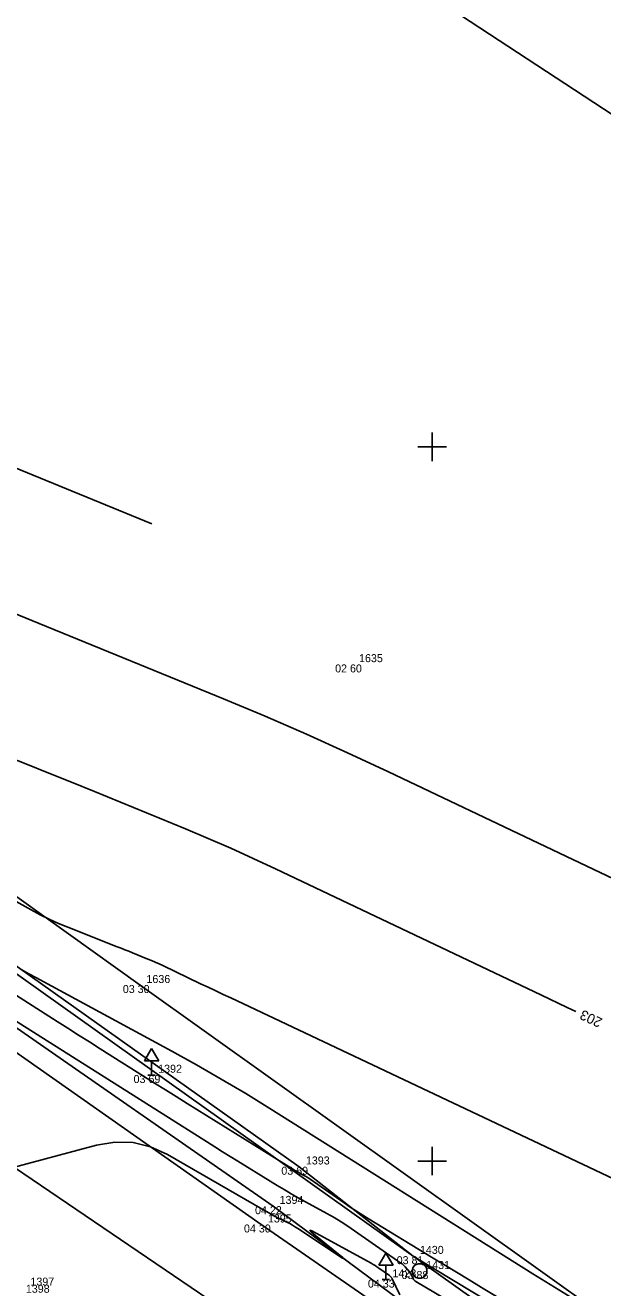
# Model space of a CAD drawing. Extents: x -711234 to -710007, y -1026313 to -1025448.
# Drawn here: x -710514.24 to -710494.03, y -1025579.43 to -1025535.25 of the extents above; entities that cross this region are included whole.
import ezdxf

# ---------------------------------------------------------------- set-up
doc = ezdxf.new("R2010")
doc.units = 0
for name, color, linetype in [('Ex_Contour Labels', 7, 'Continuous'), ('Ex_Major Contours', 7, 'Continuous'), ('Ex_Minor Contours', 7, 'Continuous'), ('Z_body', 7, 'Continuous'), ('Z_body_cisla', 7, 'Continuous'), ('Z_body_vysky_redukovane', 7, 'Continuous'), ('Z_dopravni_znacky', 7, 'Continuous'), ('Z_hektometricka_sit', 7, 'Continuous'), ('Z_hrany_paty', 7, 'Continuous'), ('Z_katastr_hranice', 7, 'Continuous'), ('Z_komunikace', 7, 'Continuous'), ('Z_komunikace_osa', 7, 'Continuous'), ('Z_pole_rozhranni', 7, 'Continuous'), ('Z_site_kanalizace_znaky', 7, 'Continuous')]:
    doc.layers.add(name, color=color, linetype=linetype)

# ---------------------------------------------------------------- blocks, each defined once
blk = doc.blocks.new('POINT_DISPLAY')
blk.add_line((0, 0), (0, 0))
blk = doc.blocks.new('Z620')
for p, q in [((-0.25, 0.05), (-0.23, 0.13)), ((-0.25, -0.05), (-0.25, 0.05)), ((-0.23, 0.13), (-0.17, 0.2)), ((-0.17, 0.2), (-0.05, 0.25)), ((-0.05, 0.25), (0.05, 0.25)), ((0.05, 0.25), (0.17, 0.2)), ((0.17, 0.2), (0.23, 0.13)), ((0.23, 0.13), (0.25, 0.05)), ((0.25, 0.05), (0.25, -0.05)), ((-0.2, -0.17), (-0.25, -0.05)), ((-0.13, -0.23), (-0.2, -0.17)), ((-0.05, -0.25), (-0.13, -0.23)), ((0.05, -0.25), (-0.05, -0.25)), ((0.13, -0.23), (0.05, -0.25)), ((0.2, -0.17), (0.13, -0.23)), ((0.25, -0.05), (0.2, -0.17))]:
    blk.add_line(p, q)
blk = doc.blocks.new('Z527')
for p, q in [((0, 0.93), (-0.25, 0.5)), ((0.25, 0.5), (0, 0.93)), ((-0.25, 0.5), (0.25, 0.5)), ((0, 0), (0, 0.5)), ((-0.13, 0), (0.13, 0))]:
    blk.add_line(p, q)

msp = doc.modelspace()

# ---------------------------------------------------------------- linework, layer by layer
at = {"layer": 'Ex_Major Contours'}
for points in [[(-710515.021, -1025560.786), (-710514.219, -1025561.103), (-710513.418, -1025561.422), (-710512.619, -1025561.744), (-710511.821, -1025562.07), (-710508.631, -1025563.378), (-710507.836, -1025563.71), (-710507.045, -1025564.053), (-710506.26, -1025564.407), (-710505.479, -1025564.772), (-710496.199, -1025569.186), (-710495.275, -1025569.625), (-710494.974, -1025569.768)], [(-710517.324, -1025568.366), (-710507.868, -1025574.338), (-710507.601, -1025574.506), (-710507.334, -1025574.674), (-710507.066, -1025574.841), (-710506.798, -1025575.008), (-710505.675, -1025575.705), (-710505.43, -1025575.855), (-710505.184, -1025576.001), (-710504.936, -1025576.144), (-710504.687, -1025576.284), (-710503.684, -1025576.837), (-710503.435, -1025576.978), (-710503.19, -1025577.126), (-710502.95, -1025577.28), (-710502.713, -1025577.441), (-710501.092, -1025578.573), (-710501.052, -1025578.603), (-710501.015, -1025578.634), (-710500.98, -1025578.668), (-710500.947, -1025578.705), (-710500.799, -1025578.878), (-710500.778, -1025578.905), (-710500.758, -1025578.932), (-710500.741, -1025578.961), (-710500.725, -1025578.992), (-710500.666, -1025579.115), (-710500.65, -1025579.144), (-710500.63, -1025579.169), (-710500.606, -1025579.192), (-710500.578, -1025579.211), (-710495.929, -1025581.975)]]:
    msp.add_lwpolyline(points, dxfattribs=at)
at = {"layer": 'Ex_Minor Contours'}
for points in [[(-710543.059, -1025536.078), (-710542.36, -1025536.464), (-710541.661, -1025536.849), (-710540.962, -1025537.234), (-710540.263, -1025537.62), (-710537.467, -1025539.162), (-710536.768, -1025539.548), (-710536.07, -1025539.935), (-710535.372, -1025540.323), (-710534.675, -1025540.712), (-710523.071, -1025547.206), (-710522.657, -1025547.429), (-710522.235, -1025547.637), (-710521.807, -1025547.831), (-710521.372, -1025548.01), (-710519.619, -1025548.698), (-710519.181, -1025548.871), (-710518.743, -1025549.045), (-710518.307, -1025549.222), (-710517.871, -1025549.399), (-710509.81, -1025552.704)], [(-710490.545, -1025566.606), (-710501.528, -1025561.382), (-710502.96, -1025560.713), (-710504.4, -1025560.064), (-710505.849, -1025559.435), (-710507.306, -1025558.825), (-710513.755, -1025556.182), (-710514.918, -1025555.708), (-710516.083, -1025555.238), (-710517.249, -1025554.773), (-710518.417, -1025554.312), (-710523.552, -1025552.297), (-710524.484, -1025551.913), (-710525.402, -1025551.498), (-710526.304, -1025551.052), (-710527.192, -1025550.575), (-710530.715, -1025548.603), (-710531.596, -1025548.111), (-710532.478, -1025547.62), (-710533.36, -1025547.131), (-710534.244, -1025546.643), (-710543.487, -1025541.545)], [(-710521.316, -1025562.171), (-710514.038, -1025566.212), (-710513.723, -1025566.38), (-710513.403, -1025566.537), (-710513.078, -1025566.684), (-710512.748, -1025566.82), (-710511.02, -1025567.498), (-710510.886, -1025567.55), (-710510.753, -1025567.604), (-710510.62, -1025567.657), (-710510.487, -1025567.712), (-710509.955, -1025567.93), (-710509.823, -1025567.985), (-710509.691, -1025568.042), (-710509.56, -1025568.101), (-710509.43, -1025568.162), (-710508.104, -1025568.793), (-710507.839, -1025568.918), (-710507.575, -1025569.044), (-710507.311, -1025569.169), (-710507.046, -1025569.294), (-710492.348, -1025576.24)], [(-710488.428, -1025585.358), (-710498.27, -1025579.421), (-710498.709, -1025579.156), (-710499.148, -1025578.891), (-710499.587, -1025578.625), (-710500.025, -1025578.36), (-710502.209, -1025577.035), (-710502.431, -1025576.898), (-710502.65, -1025576.758), (-710502.868, -1025576.614), (-710503.083, -1025576.466), (-710504.275, -1025575.634), (-710504.321, -1025575.603), (-710504.367, -1025575.573), (-710504.415, -1025575.544), (-710504.463, -1025575.517), (-710504.657, -1025575.41), (-710504.705, -1025575.383), (-710504.753, -1025575.355), (-710504.801, -1025575.327), (-710504.848, -1025575.298), (-710508.577, -1025572.983), (-710508.958, -1025572.746), (-710509.338, -1025572.508), (-710509.718, -1025572.27), (-710510.097, -1025572.031), (-710511.614, -1025571.073), (-710511.993, -1025570.833), (-710512.372, -1025570.593), (-710512.75, -1025570.352), (-710513.128, -1025570.111), (-710518.515, -1025566.672)], [(-710494.653, -1025580.07), (-710496.478, -1025578.948), (-710505.679, -1025573.161), (-710506.525, -1025572.638), (-710507.38, -1025572.13), (-710508.243, -1025571.635), (-710509.114, -1025571.155), (-710513.875, -1025568.581), (-710514.119, -1025568.447), (-710514.361, -1025568.308)], [(-710514.835, -1025575.272), (-710511.75, -1025574.448), (-710511.102, -1025574.337), (-710510.47, -1025574.354), (-710509.855, -1025574.501), (-710509.258, -1025574.777), (-710505.928, -1025576.702), (-710505.825, -1025576.76), (-710505.722, -1025576.817), (-710505.618, -1025576.872), (-710505.513, -1025576.926), (-710505.091, -1025577.137), (-710504.986, -1025577.191), (-710504.884, -1025577.248), (-710504.783, -1025577.309), (-710504.684, -1025577.373), (-710503.307, -1025578.291), (-710503.144, -1025578.396), (-710503.085, -1025578.425), (-710503.13, -1025578.378), (-710503.28, -1025578.254), (-710504.089, -1025577.605), (-710504.237, -1025577.479), (-710504.278, -1025577.425), (-710504.212, -1025577.442), (-710504.039, -1025577.531), (-710502.139, -1025578.579), (-710502.07, -1025578.618), (-710502.001, -1025578.66), (-710501.934, -1025578.703), (-710501.867, -1025578.748), (-710501.492, -1025579.01), (-710501.482, -1025579.017), (-710501.473, -1025579.025), (-710501.465, -1025579.033), (-710501.457, -1025579.042), (-710501.426, -1025579.078), (-710501.418, -1025579.088), (-710501.412, -1025579.098), (-710501.405, -1025579.108), (-710501.4, -1025579.118), (-710501.128, -1025579.688)]]:
    msp.add_lwpolyline(points, dxfattribs=at)
at = {"layer": 'Z_hektometricka_sit'}
for p, q in [((-710500, -1025549.5), (-710500, -1025550.5)), ((-710500.5, -1025550), (-710499.5, -1025550)), ((-710500, -1025574.5), (-710500, -1025575.5)), ((-710500.5, -1025575), (-710499.5, -1025575))]:
    msp.add_line(p, q, dxfattribs=at)
at = {"layer": 'Z_hrany_paty'}
for p, q in [((-710519.99, -1025564.33), (-710504.65, -1025575.2)), ((-710520.88, -1025565.94), (-710505.57, -1025576.58)), ((-710504.65, -1025575.2), (-710500.66, -1025578.33)), ((-710505.57, -1025576.58), (-710501.08, -1025579.91)), ((-710500.66, -1025578.33), (-710485.59, -1025587.42))]:
    msp.add_line(p, q, dxfattribs=at)
at = {"layer": 'Z_katastr_hranice'}
msp.add_line((-710431.64, -1025579.1), (-710574.88, -1025485.1), dxfattribs=at)
msp.add_lwpolyline([(-710600.21, -1025504.82), (-710580.45, -1025521.54), (-710492.86, -1025583.88), (-710429.93, -1025627.5), (-710391.58, -1025654.85), (-710379.57, -1025662.83), (-710367.07, -1025673.36), (-710347.9, -1025691.71), (-710333.8, -1025705.97), (-710271.15, -1025774.38), (-710237.36, -1025811.14)], dxfattribs=at)
at = {"layer": 'Z_komunikace'}
for p, q in [((-710521.13, -1025566.6), (-710505.98, -1025577.22)), ((-710505.98, -1025577.22), (-710502.12, -1025579.89))]:
    msp.add_line(p, q, dxfattribs=at)
at = {"layer": 'Z_komunikace_osa'}
msp.add_line((-710523.27, -1025569.36), (-710507.82, -1025579.85), dxfattribs=at)
at = {"layer": 'Z_pole_rozhranni'}
for p, q in [((-710528.74, -1025555.61), (-710510.22, -1025568.84)), ((-710510.22, -1025568.84), (-710492.85, -1025581.23))]:
    msp.add_line(p, q, dxfattribs=at)

# ---------------------------------------------------------------- block references
at = {"layer": 'Z_body'}
for p in [(-710502.79, -1025557.62), (-710510.22, -1025568.84), (-710509.82, -1025571.99), (-710504.65, -1025575.2), (-710505.57, -1025576.58), (-710505.98, -1025577.22), (-710500.66, -1025578.33), (-710500.44, -1025578.85), (-710501.62, -1025579.15)]:
    msp.add_blockref('POINT_DISPLAY', p, dxfattribs=at)
at = {"layer": 'Z_dopravni_znacky'}
for p in [(-710509.82, -1025571.99), (-710501.62, -1025579.15)]:
    msp.add_blockref('Z527', p, dxfattribs=at)
at = {"layer": 'Z_site_kanalizace_znaky'}
msp.add_blockref('Z620', (-710500.44, -1025578.85), dxfattribs=at)

# ---------------------------------------------------------------- texts
at = {"layer": 'Ex_Contour Labels'}
msp.add_text('203', height=0.35, rotation=154.6289, dxfattribs=at).set_placement((-710494.016, -1025570.029))
at = {"layer": 'Z_body_cisla'}
for s, p in [('1635', (-710502.56, -1025557.54)), ('1636', (-710510, -1025568.77)), ('1392', (-710509.59, -1025571.91)), ('1393', (-710504.42, -1025575.12)), ('1394', (-710505.34, -1025576.5)), ('1395', (-710505.75, -1025577.15)), ('1430', (-710500.43, -1025578.25)), ('1428', (-710501.39, -1025579.07)), ('1431', (-710500.21, -1025578.78)), ('1398', (-710514.22, -1025579.61)), ('1397', (-710514.06, -1025579.36))]:
    msp.add_text(s, height=0.28, dxfattribs=at).set_placement(p)
at = {"layer": 'Z_body_vysky_redukovane'}
for s, p in [('02 60', (-710503.397, -1025557.9)), ('03 30', (-710510.827, -1025569.12)), ('03 69', (-710510.45, -1025572.27)), ('03 69', (-710505.28, -1025575.48)), ('04 22', (-710506.2, -1025576.86)), ('04 30', (-710506.587, -1025577.5)), ('03 81', (-710501.243, -1025578.61)), ('03 88', (-710501.07, -1025579.13)), ('04 33', (-710502.25, -1025579.43))]:
    msp.add_text(s, height=0.28, dxfattribs=at).set_placement(p)

doc.saveas('drawing.dxf')
